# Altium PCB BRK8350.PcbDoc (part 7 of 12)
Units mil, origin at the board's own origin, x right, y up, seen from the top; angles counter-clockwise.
Board outline 9448.82 x 5905.51 mil, 8 copper layers (L1-TOP, L2-GND, L3-SIG, L4-GND, L5-PWR, L6-PWR, L7-GND, L8-BOT), stack 57.69 mil thick; 288 components, 543 nets, 1891 pads, 2032 vias.
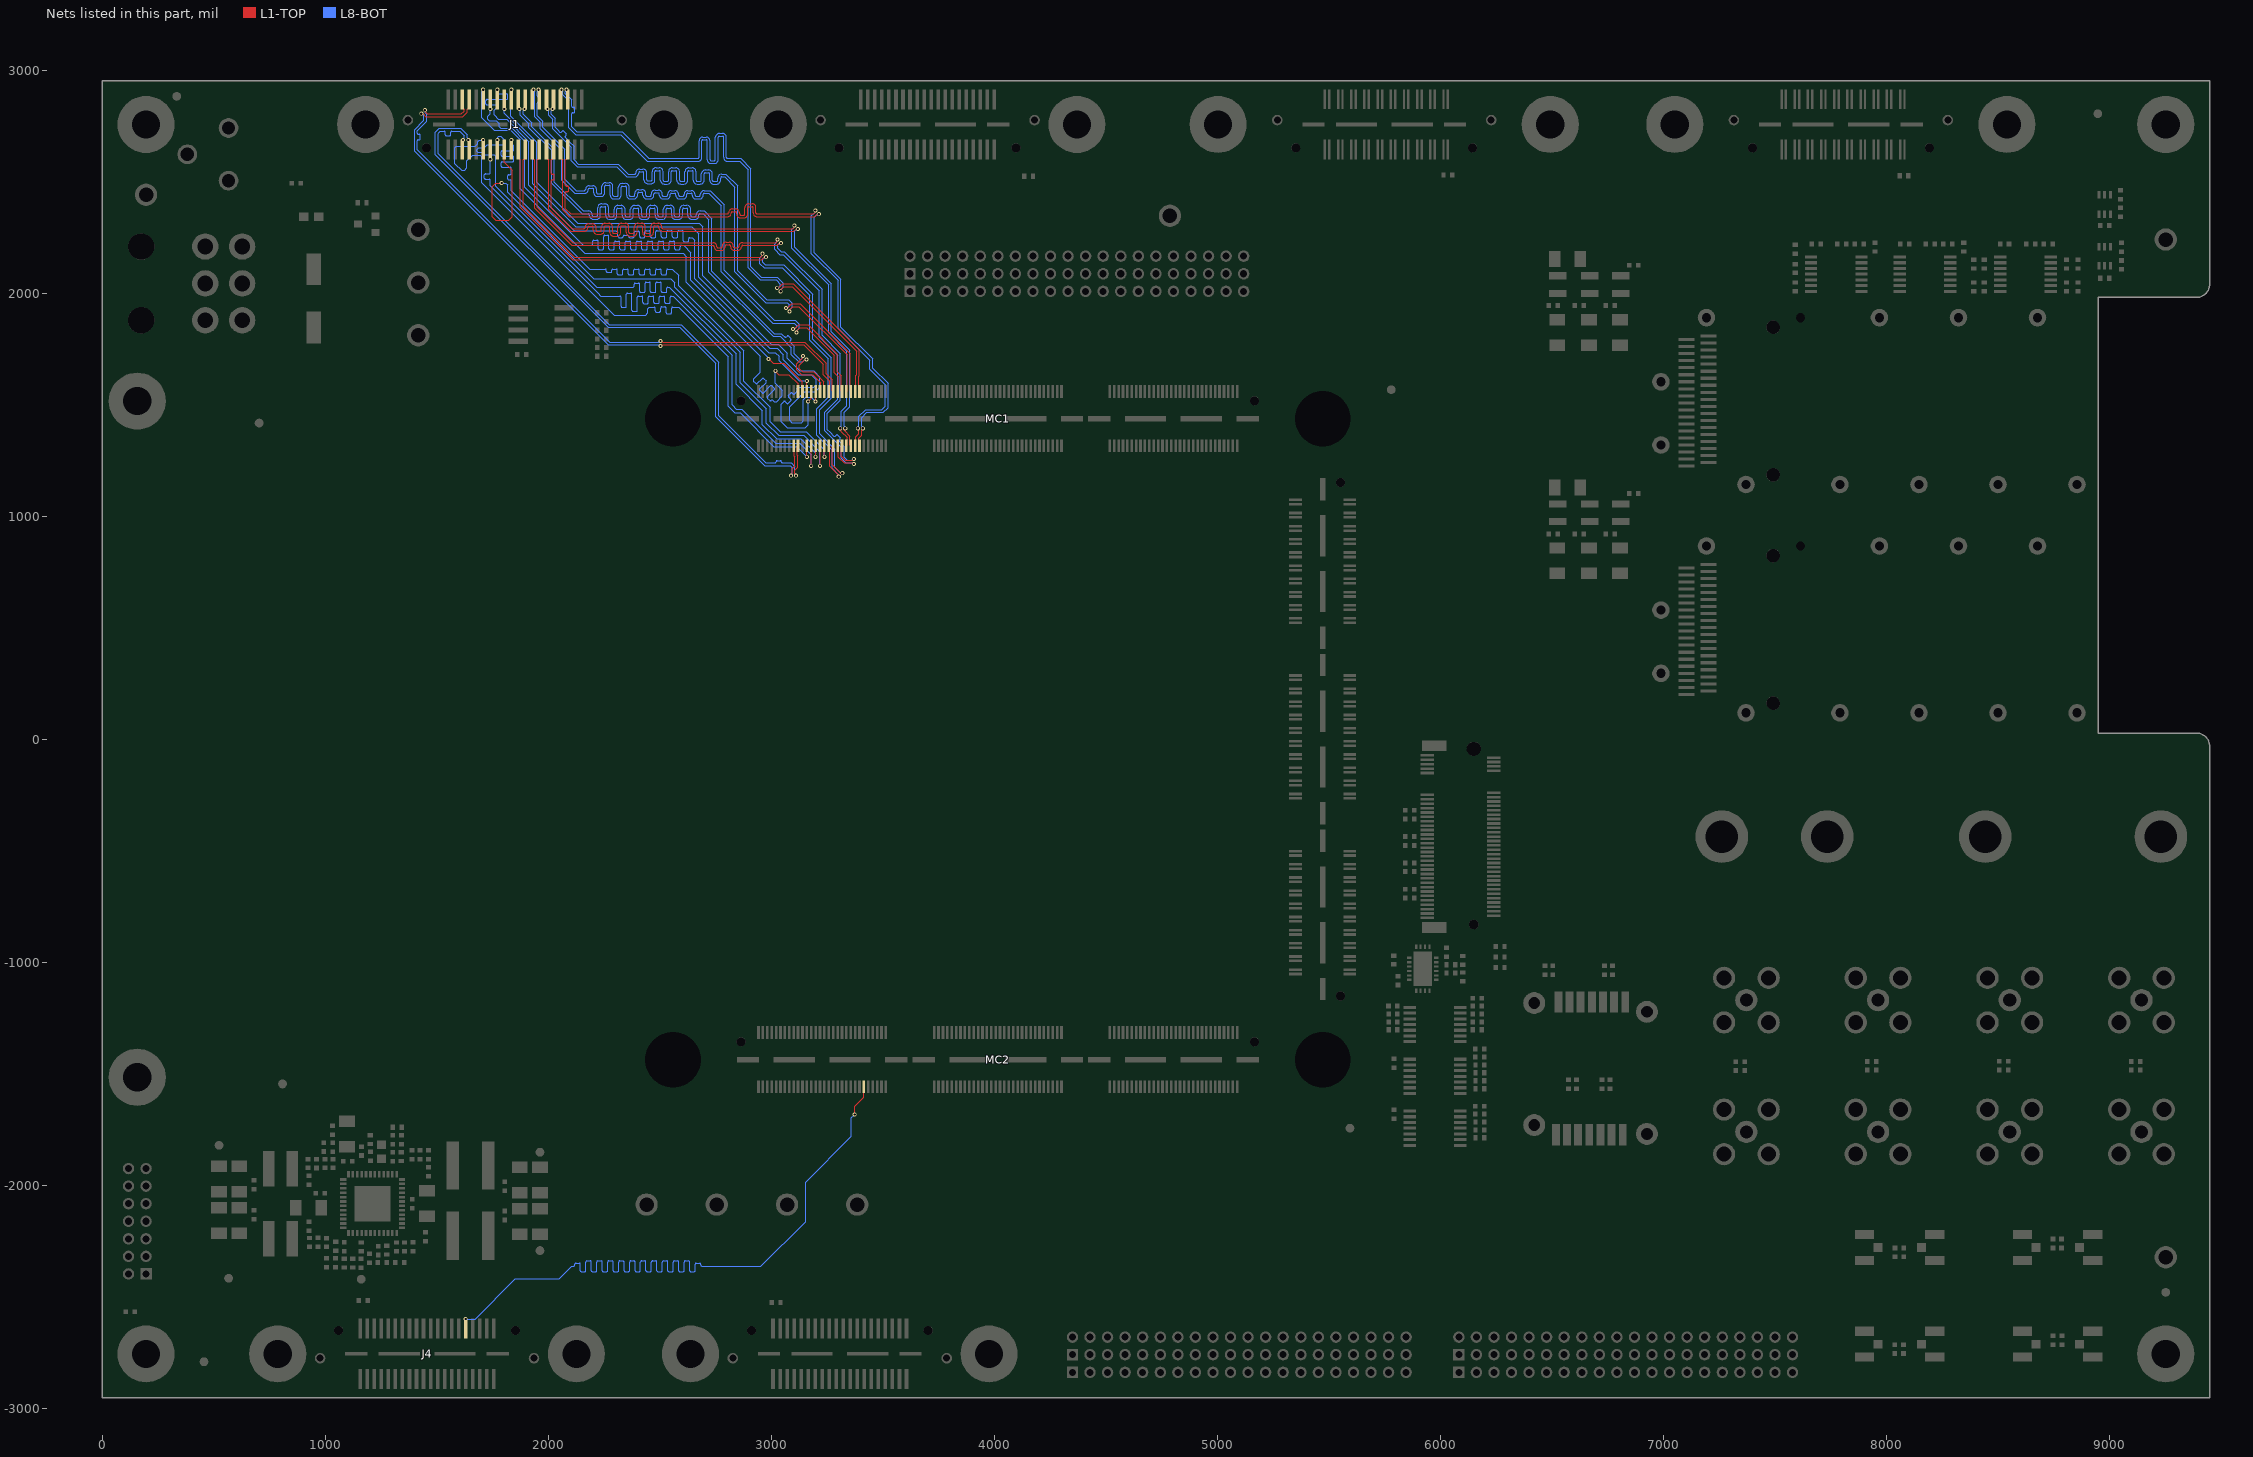
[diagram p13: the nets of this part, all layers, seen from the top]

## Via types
v1: diameter 18, hole 10, L1-TOP to L8-BOT, tented both sides, 2032 vias

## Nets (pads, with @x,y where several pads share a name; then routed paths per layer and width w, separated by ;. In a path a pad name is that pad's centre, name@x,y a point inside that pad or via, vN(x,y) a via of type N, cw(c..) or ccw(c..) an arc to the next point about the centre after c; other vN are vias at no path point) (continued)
PORTB_S27: J4.32 MC2.50 | length 3378.9
  L1-TOP w4.5: v1(3374.02,-1683.29) 3374.02,-1646.26 3415.37,-1604.9 MC2.50@3415.37,-1558.65
  L8-BOT w4.5: v1(1630.04,-2599.76) 1671.9,-2599.76 1852.83,-2418.83 2049.72,-2418.83 2106.34,-2362.2 2112.52,-2362.2 2114.77,-2362.2 ccw(c2114.77,-2357.3) 2119.67,-2357.3 2119.67,-2353.77 cw(c2124.57,-2353.77) 2124.57,-2348.87 2139.27,-2348.87 cw(c2139.27,-2353.77) 2144.17,-2353.77 2144.17,-2382.3 ccw(c2149.07,-2382.3) 2149.07,-2387.2 2163.77,-2387.2 ccw(c2163.77,-2382.3) 2168.67,-2382.3 2168.67,-2344.23 cw(c2173.57,-2344.23) 2173.57,-2339.33 2188.27,-2339.33 cw(c2188.27,-2344.23) 2193.17,-2344.23 2193.17,-2382.3 ccw(c2198.07,-2382.3) 2198.07,-2387.2 2212.77,-2387.2 ccw(c2212.77,-2382.3) 2217.67,-2382.3 2217.67,-2344.23 cw(c2222.57,-2344.23) 2222.57,-2339.33 2237.27,-2339.33 cw(c2237.27,-2344.23) 2242.17,-2344.23 2242.17,-2382.3 ccw(c2247.07,-2382.3) 2247.07,-2387.2 2261.77,-2387.2 ccw(c2261.77,-2382.3) 2266.67,-2382.3 2266.67,-2344.23 cw(c2271.57,-2344.23) 2271.57,-2339.33 2286.27,-2339.33 cw(c2286.27,-2344.23) 2291.17,-2344.23 2291.17,-2382.3 ccw(c2296.07,-2382.3) 2296.07,-2387.2 2310.77,-2387.2 ccw(c2310.77,-2382.3) 2315.67,-2382.3 2315.67,-2344.23 cw(c2320.57,-2344.23) 2320.57,-2339.33 2335.27,-2339.33 cw(c2335.27,-2344.23) 2340.17,-2344.23 2340.17,-2382.3 ccw(c2345.07,-2382.3) 2345.07,-2387.2 2359.77,-2387.2 ccw(c2359.77,-2382.3) 2364.67,-2382.3 2364.67,-2344.23 cw(c2369.57,-2344.23) 2369.57,-2339.33 2384.27,-2339.33 cw(c2384.27,-2344.23) 2389.17,-2344.23 2389.17,-2382.3 ccw(c2394.07,-2382.3) 2394.07,-2387.2 2408.77,-2387.2 ccw(c2408.77,-2382.3) 2413.67,-2382.3 2413.67,-2344.23 cw(c2418.57,-2344.23) 2418.57,-2339.33 2433.27,-2339.33 cw(c2433.27,-2344.23) 2438.17,-2344.23 2438.17,-2382.3 ccw(c2443.07,-2382.3) 2443.07,-2387.2 2457.77,-2387.2 ccw(c2457.77,-2382.3) 2462.67,-2382.3 2462.67,-2344.23 cw(c2467.57,-2344.23) 2467.57,-2339.33 2482.27,-2339.33 cw(c2482.27,-2344.23) 2487.17,-2344.23 2487.17,-2382.3 ccw(c2492.07,-2382.3) 2492.07,-2387.2 2506.77,-2387.2 ccw(c2506.77,-2382.3) 2511.67,-2382.3 2511.67,-2344.23 cw(c2516.57,-2344.23) 2516.57,-2339.33 2531.27,-2339.33 cw(c2531.27,-2344.23) 2536.17,-2344.23 2536.17,-2382.3 ccw(c2541.07,-2382.3) 2541.07,-2387.2 2555.77,-2387.2 ccw(c2555.77,-2382.3) 2560.67,-2382.3 2560.67,-2344.23 cw(c2565.57,-2344.23) 2565.57,-2339.33 2580.27,-2339.33 cw(c2580.27,-2344.23) 2585.17,-2344.23 2585.17,-2382.3 ccw(c2590.07,-2382.3) 2590.07,-2387.2 2604.77,-2387.2 ccw(c2604.77,-2382.3) 2609.67,-2382.3 2609.67,-2344.23 cw(c2614.57,-2344.23) 2614.57,-2339.33 2629.27,-2339.33 cw(c2629.27,-2344.23) 2634.17,-2344.23 2634.17,-2382.3 ccw(c2639.07,-2382.3) 2639.07,-2387.2 2653.77,-2387.2 ccw(c2653.77,-2382.3) 2658.67,-2382.3 2658.67,-2353.66 cw(c2663.57,-2353.66) 2663.57,-2348.76 2678.27,-2348.76 cw(c2678.27,-2353.66) 2683.17,-2353.66 2683.17,-2357.3 ccw(c2688.07,-2357.3) 2688.07,-2362.2 2755.91,-2362.2 2953.94,-2362.2 ; 2955.32,-2360.83 2953.94,-2362.2 ; v1(3374.02,-1683.29) 3359.67,-1697.64 3359.67,-1781.45 3153.54,-1987.58 3153.54,-2162.6 2953.94,-2362.2
PORTC_C2P_CLKN: J1.36 MC1.20 | length 2791.7
  L1-TOP w4.2: v1(3111.25,1181.1) 3111.25,1184.03 3106.3,1188.98 3106.3,1206.59 3118.98,1219.27 3118.98,1271.53 3116.55,1273.96 3116.55,1311.83 MC1.20@3120.09,1315.37
  L8-BOT w4.2: v1(1618.46,2686.46) 1618.46,2690.2 1623.69,2695.43 1623.69,2705.34 1603.62,2725.42 1582.48,2725.42 1567.44,2725.42 ccw(c1567.44,2720.58) 1562.6,2720.58 1562.6,2710.76 cw(c1557.76,2710.76) 1557.76,2705.92 1543.24,2705.92 cw(c1543.24,2710.76) 1538.4,2710.76 1538.4,2720.58 ccw(c1533.56,2720.58) 1533.56,2725.42 1516,2725.42 1509.68,2719.09 1505.88,2715.3 1505.88,2625.74 2273.35,1858.27 2595.94,1858.27 2764.57,1689.64 2764.57,1450.65 2953,1262.21 2976.04,1239.17 2988.19,1239.17 3016.49,1239.17 ccw(c3016.49,1244.01) 3021.33,1244.01 cw(c3026.17,1244.01) 3026.17,1248.85 3040.69,1248.85 cw(c3040.69,1244.01) 3045.53,1244.01 ccw(c3050.37,1244.01) 3050.37,1239.17 3076.67,1239.17 3089.36,1239.17 3106.3,1222.24 3106.3,1189.79 3111.25,1184.84 v1(3111.25,1181.1)
PORTC_C2P_CLKP: J1.34 MC1.18 | length 2791.7
  L1-TOP w4.2: v1(3088.75,1181.1) 3088.75,1184.03 3093.7,1188.98 3093.7,1211.81 3106.38,1224.49 3106.38,1266.31 3103.95,1268.74 3103.95,1311.83 MC1.18@3100.41,1315.37
  L8-BOT w4.2: v1(1641.53,2686.46) 1641.53,2690.2 1636.29,2695.43 1636.29,2710.56 1608.84,2738.02 1510.78,2738.02 1500.77,2728 1493.28,2720.52 1493.28,2704.84 1493.28,2620.52 1561.63,2552.17 2268.13,1845.67 2590.72,1845.67 2751.97,1684.42 2751.97,1445.43 2905.51,1291.88 2935.18,1262.21 2970.82,1226.57 3084.15,1226.57 3093.7,1217.02 3093.7,1189.79 3088.75,1184.84 v1(3088.75,1181.1)
PORTC_P2C_CLKN: J1.35 MC1.35 | length 2839.8
  L1-TOP w4.2: v1(1446.88,2819.96) 1447.83,2819.01 1447.83,2812.01 1456.63,2803.21 1610.55,2803.21 1623.64,2816.31 1623.64,2823.6 1621.18,2826.06 1620.09,2826.06 1614.19,2831.96 J1.35@1614.19,2868.71 ; v1(2503.94,1785.27) 2507.67,1785.27 2512.62,1780.32 3150.65,1780.32 3245.85,1685.11 3245.85,1638.71 3250.71,1633.86 3250.8,1633.86 3274.03,1610.63 3274.03,1562.22 MC1.35@3277.57,1558.68
  L8-BOT w4.2: v1(1446.88,2819.96) 1448.13,2818.71 1448.13,2808.86 1454.72,2802.27 1454.72,2769.38 1413.19,2727.85 1413.19,2723.96 1413.19,2716.64 ccw(c1418.03,2716.64) 1418.03,2711.8 1421.7,2711.8 cw(c1421.7,2706.96) 1426.54,2706.96 1426.53,2692.44 cw(c1421.7,2692.44) 1421.7,2687.6 1418.03,2687.6 ccw(c1418.03,2682.76) 1413.19,2682.76 1413.19,2656.46 1413.19,2641.93 1454.72,2600.39 1502.95,2552.17 2274.8,1780.32 2495.25,1780.32 2500.2,1785.27 v1(2503.94,1785.27)
PORTC_P2C_CLKP: J1.33 MC1.33 | length 2840.6
  L1-TOP w4.2: v1(1430.97,2804.05) 1431.92,2803.1 1438.93,2803.1 1451.41,2790.61 1615.77,2790.61 1636.24,2811.09 1636.24,2823.6 1638.7,2826.06 1639.79,2826.06 1645.69,2831.96 J1.33@1645.69,2868.71 ; v1(2503.94,1762.77) 2507.67,1762.77 2512.62,1767.72 3145.43,1767.72 3233.25,1679.9 3233.25,1633.86 3233.25,1633.5 3245.49,1621.26 3245.58,1621.26 3261.43,1605.41 3261.43,1562.22 MC1.33@3257.89,1558.68
  L8-BOT w4.2: v1(1430.97,2804.05) 1434.7,2804.05 1439.25,2799.51 1439.66,2799.51 1442.12,2797.05 1442.12,2774.6 1400.59,2733.07 1400.59,2636.71 1454.72,2582.57 1485.13,2552.17 2269.58,1767.72 2495.25,1767.72 2500.2,1762.77 v1(2503.94,1762.77)
PORTC_S0_D0P: J1.5 MC1.45 | length 2793.1
  L1-TOP w4.2: v1(3042.35,2007.79) 3043.31,2008.75 3043.31,2015.75 3056.72,2029.16 3093.06,2029.16 3382.24,1739.99 3382.24,1633.86 3379.81,1631.43 3379.81,1562.48 MC1.45@3376,1558.68
  L8-BOT w4.2: v1(2082.53,2912.06) 2082.53,2908.33 2077.29,2903.09 2077.29,2894.33 2105.14,2866.48 2105.14,2856.88 2105.14,2837.74 ccw(c2109.98,2837.74) 2109.98,2832.9 2114.87,2832.9 cw(c2114.87,2828.06) 2119.71,2828.06 2119.71,2813.54 cw(c2114.87,2813.54) 2114.87,2808.7 2109.98,2808.7 ccw(c2109.98,2803.86) 2105.14,2803.86 2105.14,2777.56 2105.14,2745.34 2128.21,2722.27 2330.98,2722.27 2449.63,2603.62 2579.72,2603.62 2671.21,2603.62 ccw(c2671.21,2608.46) 2676.05,2608.46 2676.05,2682.04 cw(c2693.49,2682.04) 2693.49,2699.48 2708.01,2699.48 cw(c2708.01,2682.04) 2725.45,2682.04 2725.45,2598.64 ccw(c2730.29,2598.64) 2730.29,2593.8 2744.81,2593.8 ccw(c2744.81,2598.64) 2749.65,2598.64 2749.65,2698.32 cw(c2767.09,2698.32) 2767.09,2715.76 2781.61,2715.76 cw(c2781.61,2698.32) 2799.05,2698.32 2799.05,2608.46 ccw(c2803.89,2608.46) 2803.89,2603.62 2849.1,2603.62 2862.91,2603.62 2908.7,2557.84 2908.7,2117.7 2954.75,2071.66 3026.77,2071.66 3053.36,2045.06 3053.36,2025.8 3044.99,2017.43 3044.99,2010.43 v1(3042.35,2007.79)
PORTC_S1_D1P: J1.6 MC1.46 | length 2840.6
  L1-TOP w4.2: J1.6@2086.69,2643.11 2086.69,2606.36 2080.79,2600.46 2079.7,2600.46 2077.24,2598 2077.24,2509.43 2077.24,2484.39 ccw(c2082.08,2484.39) 2082.08,2479.55 2087,2479.55 cw(c2087,2474.71) 2091.84,2474.71 2091.84,2460.19 cw(c2087,2460.19) 2087,2455.35 2082.08,2455.35 ccw(c2082.08,2450.51) 2077.24,2450.51 2077.24,2424.21 2077.24,2377.76 2099.88,2355.12 2750,2355.12 2803.42,2355.12 ccw(c2803.42,2359.96) 2808.26,2359.96 cw(c2825.7,2359.96) 2825.7,2377.4 2840.22,2377.4 cw(c2840.22,2359.96) 2857.66,2359.96 2857.66,2354.72 ccw(c2862.5,2354.72) 2862.5,2349.88 2877.02,2349.88 ccw(c2877.02,2354.72) 2881.86,2354.72 2881.86,2383.26 cw(c2899.3,2383.26) 2899.3,2400.7 2913.82,2400.7 cw(c2913.82,2383.26) 2931.26,2383.26 2931.26,2359.96 ccw(c2936.1,2359.96) 2936.1,2355.12 2981.3,2355.12 3189.77,2355.12 3199.05,2364.4 3197.29,2366.16 v1(3197.29,2369.64) ; MC1.46@3376,1315.37 3379.54,1318.91 3379.54,1355.43 3392.91,1368.8 3392.91,1385.02 3387.96,1389.97 v1(3387.96,1393.7)
  L8-BOT w4.2: v1(3197.29,2369.64) 3194.65,2367 3194.65,2360 3180.31,2345.67 3180.31,2175.88 3299.38,2056.81 3299.38,2027.84 3299.38,1842.07 3397.73,1743.72 3442.12,1699.33 3442.12,1658.27 3510.83,1589.57 3510.83,1492.13 3495.92,1477.22 3422.98,1477.22 3392.91,1447.15 3392.91,1402.39 3387.96,1397.44 v1(3387.96,1393.7)
PORTC_S2_D0N: J1.7 MC1.47 | length 2792.9
  L1-TOP w4.2: v1(3026.44,2023.7) 3027.4,2024.66 3034.4,2024.66 3051.5,2041.76 3098.28,2041.76 3394.84,1745.21 3394.84,1628.64 3392.41,1626.21 3392.41,1561.96 MC1.47@3395.69,1558.68
  L8-BOT w4.2: v1(2059.46,2912.06) 2059.46,2908.33 2064.69,2903.09 2064.69,2889.11 2092.54,2861.26 2092.54,2740.12 2123,2709.67 2325.76,2709.67 2444.41,2591.02 2579.72,2591.02 2671.21,2591.02 ccw(c2671.21,2608.46) 2688.65,2608.46 2688.65,2682.04 cw(c2693.49,2682.04) 2693.49,2686.88 2708.01,2686.88 cw(c2708.01,2682.04) 2712.85,2682.04 2712.85,2598.64 ccw(c2730.29,2598.64) 2730.29,2581.2 2744.81,2581.2 ccw(c2744.81,2598.64) 2762.25,2598.64 2762.25,2698.32 cw(c2767.09,2698.32) 2767.09,2703.16 2781.61,2703.15 cw(c2781.61,2698.32) 2786.45,2698.32 2786.45,2608.46 ccw(c2803.89,2608.46) 2803.89,2591.02 2849.1,2591.02 2857.7,2591.02 2896.1,2552.62 2896.1,2112.48 2949.53,2059.06 3021.55,2059.06 3040.76,2039.84 3040.76,2031.02 3036.08,2026.34 3029.08,2026.34 v1(3026.44,2023.7)
PORTC_S3_D1N: J1.8 MC1.48 | length 2840.6
  L1-TOP w4.2: J1.8@2055.19,2643.11 2055.19,2606.36 2061.09,2600.46 2062.18,2600.46 2064.64,2598 2064.64,2372.54 2094.66,2342.52 2750,2342.52 2803.42,2342.52 ccw(c2803.42,2359.96) 2820.86,2359.96 cw(c2825.7,2359.96) 2825.7,2364.8 2840.22,2364.8 cw(c2840.22,2359.96) 2845.06,2359.96 2845.06,2354.72 ccw(c2862.5,2354.72) 2862.5,2337.28 2877.02,2337.28 ccw(c2877.02,2354.72) 2894.46,2354.72 2894.46,2383.26 cw(c2899.3,2383.26) 2899.3,2388.1 2913.82,2388.1 cw(c2913.82,2383.26) 2918.66,2383.26 2918.66,2359.96 ccw(c2936.1,2359.96) 2936.1,2342.52 2981.3,2342.52 3194.98,2342.52 3207.96,2355.49 3211.44,2355.49 v1(3213.2,2353.73) ; MC1.48@3395.69,1315.37 3392.14,1318.91 3392.14,1350.21 3405.51,1363.58 3405.51,1385.02 3410.46,1389.97 v1(3410.46,1393.7)
  L8-BOT w4.2: v1(3213.2,2353.73) 3210.56,2351.09 3203.56,2351.09 3192.91,2340.45 3192.91,2181.1 3311.98,2062.03 3311.98,1847.29 3454.72,1704.55 3454.72,1663.49 3523.43,1594.79 3523.43,1486.91 3501.14,1464.62 3428.2,1464.62 3405.51,1441.93 3405.51,1402.39 3410.46,1397.44 v1(3410.46,1393.7)
PORTC_S4_D2P: J1.9 MC1.41 | length 2793.1
  L1-TOP w4.2: v1(3081.72,1917.24) 3082.68,1918.2 3082.68,1925.2 3096.81,1939.33 3123.78,1939.33 3340.44,1722.67 3340.44,1562.48 MC1.41@3336.63,1558.68
  L8-BOT w4.2: v1(2019.43,2825.35) 2019.43,2821.61 2014.19,2816.38 2014.19,2801.72 2032.22,2783.69 2032.22,2742.52 2043.51,2731.23 2052.66,2722.09 ccw(c2056.08,2725.51) 2059.5,2722.09 2062.95,2725.53 cw(c2066.37,2722.11) 2069.8,2725.53 2080.06,2715.27 cw(c2076.64,2711.84) 2080.06,2708.42 2076.62,2704.97 ccw(c2080.04,2701.55) 2076.62,2698.13 2095.21,2679.53 2115.7,2659.04 2115.7,2597.88 2135.04,2578.54 2247.05,2578.54 2312.99,2578.54 2358.27,2533.27 2387.55,2533.27 ccw(c2387.55,2538.11) 2392.39,2538.11 cw(c2409.83,2538.11) 2409.83,2555.55 2424.35,2555.55 cw(c2424.35,2538.11) 2441.79,2538.11 2441.79,2507.94 ccw(c2446.63,2507.94) 2446.63,2503.1 2461.15,2503.1 ccw(c2461.15,2507.94) 2465.99,2507.94 2465.99,2544.38 cw(c2483.43,2544.38) 2483.43,2561.82 2497.95,2561.82 cw(c2497.95,2544.38) 2515.39,2544.38 2515.39,2506.29 ccw(c2520.23,2506.29) 2520.23,2501.45 2534.75,2501.45 ccw(c2534.75,2506.29) 2539.59,2506.29 2539.59,2544.38 cw(c2557.03,2544.38) 2557.03,2561.82 2571.55,2561.82 cw(c2571.55,2544.38) 2588.99,2544.38 2588.99,2506.29 ccw(c2593.83,2506.29) 2593.83,2501.45 2608.35,2501.45 ccw(c2608.35,2506.29) 2613.19,2506.29 2613.19,2544.38 cw(c2630.63,2544.38) 2630.63,2561.82 2645.15,2561.82 cw(c2645.15,2544.38) 2662.59,2544.38 2662.59,2506.29 ccw(c2667.43,2506.29) 2667.43,2501.45 2681.95,2501.45 ccw(c2681.95,2506.29) 2686.79,2506.29 2686.79,2534.56 cw(c2704.23,2534.56) 2704.23,2552 2718.75,2552 cw(c2718.75,2534.56) 2736.19,2534.56 2736.19,2506.03 ccw(c2741.03,2506.03) 2741.03,2501.19 2755.55,2501.19 ccw(c2755.55,2506.03) 2760.39,2506.03 2760.39,2515.83 cw(c2777.83,2515.83) 2777.83,2533.27 2786.23,2533.27 2796.56,2533.27 2849.41,2480.42 2849.41,2100.48 2979.65,1970.23 3077.85,1970.23 3094.32,1953.76 3094.32,1936.84 3084.36,1926.88 3084.36,1919.88 v1(3081.72,1917.24)
PORTC_S5_D3P: J1.10 MC1.42 | length 2840.2
  L1-TOP w4.2: J1.10@2023.69,2643.11 2023.69,2606.36 2017.79,2600.46 2016.7,2600.46 2014.24,2598 2014.24,2544.29 2014.24,2536.91 ccw(c2019.08,2536.91) 2019.08,2532.07 2023.06,2532.07 cw(c2023.06,2527.23) 2027.9,2527.23 2027.9,2512.71 cw(c2023.06,2512.71) 2023.06,2507.87 2019.08,2507.87 ccw(c2019.08,2503.03) 2014.24,2503.03 2014.24,2476.73 2014.24,2381.64 2106.77,2289.11 2122.67,2289.11 2160.37,2289.11 ccw(c2160.37,2293.95) 2165.21,2293.95 cw(c2182.65,2293.95) 2182.65,2311.39 2197.17,2311.39 cw(c2197.17,2293.95) 2214.61,2293.95 2214.61,2281.54 ccw(c2219.45,2281.54) 2219.45,2276.7 2233.97,2276.7 ccw(c2233.97,2281.54) 2238.81,2281.54 2238.81,2295.88 cw(c2256.25,2295.88) 2256.25,2313.32 2270.77,2313.32 cw(c2270.77,2295.88) 2288.21,2295.88 2288.21,2272.73 ccw(c2293.05,2272.73) 2293.05,2267.89 2307.57,2267.89 ccw(c2307.57,2272.73) 2312.41,2272.73 2312.41,2295.88 cw(c2329.85,2295.88) 2329.85,2313.32 2344.37,2313.32 cw(c2344.37,2295.88) 2361.81,2295.88 2361.81,2272.73 ccw(c2366.65,2272.73) 2366.65,2267.89 2381.17,2267.89 ccw(c2381.17,2272.73) 2386.01,2272.73 2386.01,2295.88 cw(c2403.45,2295.88) 2403.45,2313.32 2417.97,2313.32 cw(c2417.97,2295.88) 2435.41,2295.88 2435.41,2272.73 ccw(c2440.25,2272.73) 2440.25,2267.89 2454.77,2267.89 ccw(c2454.77,2272.73) 2459.61,2272.73 2459.61,2295.88 cw(c2477.05,2295.88) 2477.05,2313.32 2491.57,2313.32 cw(c2491.57,2295.88) 2509.01,2295.88 2509.01,2293.95 ccw(c2513.85,2293.95) 2513.85,2289.11 2559.06,2289.11 3096.2,2289.11 3102.36,2295.28 3102.36,2302.28 v1(3103.32,2303.23) ; v1(3309.22,1393.7) 3311.68,1391.24 3314.17,1391.24 3314.17,1378.74 3340.17,1352.74 3340.17,1318.91 MC1.42@3336.63,1315.37
  L8-BOT w4.2: v1(3103.32,2303.23) 3100.68,2300.59 3100.68,2293.59 3092.31,2285.22 3092.31,2200.9 3256.83,2036.38 3256.83,1822.03 3339.51,1739.35 3339.51,1495.12 3314.17,1469.79 3314.17,1402.39 3309.22,1397.44 v1(3309.22,1393.7)
PORTC_S6_D2N: J1.11 MC1.43 | length 2792.9
  L1-TOP w4.2: v1(3065.81,1933.15) 3066.77,1934.11 3073.77,1934.11 3091.59,1951.93 3129,1951.93 3353.04,1727.89 3353.04,1561.96 MC1.43@3356.31,1558.68
  L8-BOT w4.2: v1(1996.36,2825.35) 1996.36,2821.61 2001.59,2816.38 2001.59,2796.5 2019.62,2778.47 2019.62,2737.3 2086.3,2670.62 2103.1,2653.82 2103.1,2592.66 2129.82,2565.94 2247.05,2565.94 2307.77,2565.94 2353.05,2520.67 2358.27,2520.67 2387.55,2520.67 ccw(c2387.55,2538.11) 2404.99,2538.11 cw(c2409.83,2538.11) 2409.83,2542.95 2424.35,2542.95 cw(c2424.35,2538.11) 2429.19,2538.11 2429.19,2507.94 ccw(c2446.63,2507.94) 2446.63,2490.5 2461.15,2490.5 ccw(c2461.15,2507.94) 2478.59,2507.94 2478.59,2544.38 cw(c2483.43,2544.38) 2483.43,2549.22 2497.95,2549.22 cw(c2497.95,2544.38) 2502.79,2544.38 2502.79,2506.29 ccw(c2520.23,2506.29) 2520.23,2488.85 2534.75,2488.85 ccw(c2534.75,2506.29) 2552.19,2506.29 2552.19,2544.38 cw(c2557.03,2544.38) 2557.03,2549.22 2571.55,2549.22 cw(c2571.55,2544.38) 2576.39,2544.38 2576.39,2506.29 ccw(c2593.83,2506.29) 2593.83,2488.85 2608.35,2488.85 ccw(c2608.35,2506.29) 2625.79,2506.29 2625.79,2544.38 cw(c2630.63,2544.38) 2630.63,2549.22 2645.15,2549.22 cw(c2645.15,2544.38) 2649.99,2544.38 2649.99,2506.29 ccw(c2667.43,2506.29) 2667.43,2488.85 2681.95,2488.85 ccw(c2681.95,2506.29) 2699.39,2506.29 2699.39,2534.56 cw(c2704.23,2534.56) 2704.23,2539.4 2718.75,2539.4 cw(c2718.75,2534.56) 2723.59,2534.56 2723.59,2506.03 ccw(c2741.03,2506.03) 2741.03,2488.59 2755.55,2488.59 ccw(c2755.55,2506.03) 2772.99,2506.03 2772.99,2515.83 cw(c2777.83,2515.83) 2777.83,2520.67 2786.23,2520.67 2791.34,2520.67 2836.81,2475.2 2836.81,2095.26 2974.43,1957.63 3072.63,1957.63 3081.72,1948.54 3081.72,1942.06 3075.45,1935.79 3068.45,1935.79 v1(3065.81,1933.15)
PORTC_S7_D3N: J1.12 MC1.44 | length 2842.1
  L1-TOP w4.2: J1.12@1992.19,2643.11 1992.19,2606.36 1998.09,2600.46 1999.18,2600.46 2001.64,2598 2001.64,2376.42 2101.55,2276.51 2122.67,2276.51 2160.37,2276.51 ccw(c2160.37,2293.95) 2177.81,2293.95 cw(c2182.65,2293.95) 2182.65,2298.79 2197.17,2298.79 cw(c2197.17,2293.95) 2202.01,2293.95 2202.01,2281.54 ccw(c2219.45,2281.54) 2219.45,2264.1 2233.97,2264.1 ccw(c2233.97,2281.54) 2251.41,2281.54 2251.41,2295.88 cw(c2256.25,2295.88) 2256.25,2300.72 2270.77,2300.72 cw(c2270.77,2295.88) 2275.61,2295.88 2275.61,2272.73 ccw(c2293.05,2272.73) 2293.05,2255.29 2307.57,2255.29 ccw(c2307.57,2272.73) 2325.01,2272.73 2325.01,2295.88 cw(c2329.85,2295.88) 2329.85,2300.72 2344.37,2300.72 cw(c2344.37,2295.88) 2349.21,2295.88 2349.21,2272.73 ccw(c2366.65,2272.73) 2366.65,2255.29 2381.17,2255.29 ccw(c2381.17,2272.73) 2398.61,2272.73 2398.61,2295.88 cw(c2403.45,2295.88) 2403.45,2300.72 2417.97,2300.72 cw(c2417.97,2295.88) 2422.81,2295.88 2422.81,2272.73 ccw(c2440.25,2272.73) 2440.25,2255.29 2454.77,2255.29 ccw(c2454.77,2272.73) 2472.21,2272.73 2472.21,2295.88 cw(c2477.05,2295.88) 2477.05,2300.72 2491.57,2300.72 cw(c2491.57,2295.88) 2496.41,2295.88 2496.41,2293.95 ccw(c2513.85,2293.95) 2513.85,2276.51 2559.06,2276.51 3101.42,2276.51 3111.27,2286.37 3118.27,2286.37 v1(3119.23,2287.32) ; v1(3331.72,1393.7) 3329.23,1393.7 3326.77,1391.24 3326.77,1383.96 3352.77,1357.96 3352.77,1318.91 MC1.44@3356.31,1315.37
  L8-BOT w4.2: v1(3119.23,2287.32) 3116.59,2284.68 3109.59,2284.68 3104.91,2280 3104.91,2206.12 3269.43,2041.6 3269.43,1827.25 3352.11,1744.57 3352.11,1489.9 3326.77,1464.57 3326.77,1402.39 3331.72,1397.44 v1(3331.72,1393.7)
PORTC_S8_D4P: J1.13 MC1.37 | length 2793
  L1-TOP w4.2: v1(3113.22,1822.75) 3114.17,1823.71 3114.17,1830.71 3127.87,1844.41 3159.59,1844.41 3283.46,1720.53 3283.46,1642.4 3300.8,1625.06 3300.8,1562.22 MC1.37@3297.26,1558.68
  L8-BOT w4.2: v1(1956.53,2912.06) 1956.53,2908.33 1951.29,2903.09 1951.29,2894.69 1951.29,2885.53 ccw(c1956.13,2885.53) 1956.13,2880.69 1961.05,2880.69 cw(c1961.05,2875.85) 1965.89,2875.85 1965.89,2861.33 cw(c1961.05,2861.33) 1961.05,2856.49 1956.13,2856.49 ccw(c1956.13,2851.65) 1951.29,2851.65 1951.29,2825.35 1951.29,2795.72 1976.12,2770.89 1976.12,2742.52 2073.8,2644.84 2073.8,2510.47 2124.63,2459.65 2162.34,2459.65 ccw(c2162.34,2464.49) 2167.18,2464.49 cw(c2184.62,2464.49) 2184.62,2481.93 2199.14,2481.93 cw(c2199.14,2464.49) 2216.58,2464.49 2216.58,2450.65 ccw(c2221.42,2450.65) 2221.42,2445.81 2235.94,2445.81 ccw(c2235.94,2450.65) 2240.78,2450.65 2240.78,2478.24 cw(c2258.22,2478.24) 2258.22,2495.68 2272.74,2495.68 cw(c2272.74,2478.24) 2290.18,2478.24 2290.18,2439.49 ccw(c2295.02,2439.49) 2295.02,2434.65 2309.54,2434.65 ccw(c2309.54,2439.49) 2314.38,2439.49 2314.38,2474.03 cw(c2331.82,2474.03) 2331.82,2491.47 2346.34,2491.47 cw(c2346.34,2474.03) 2363.78,2474.03 2363.78,2439.49 ccw(c2368.62,2439.49) 2368.62,2434.65 2383.14,2434.65 ccw(c2383.14,2439.49) 2387.98,2439.49 2387.98,2446.19 cw(c2405.42,2446.19) 2405.42,2463.63 2419.94,2463.63 cw(c2419.94,2446.19) 2437.38,2446.19 2437.38,2439.49 ccw(c2442.22,2439.49) 2442.22,2434.65 2456.74,2434.65 ccw(c2456.74,2439.49) 2461.58,2439.49 2461.58,2443.86 cw(c2479.02,2443.86) 2479.02,2461.3 2493.54,2461.3 cw(c2493.54,2443.86) 2510.98,2443.86 2510.98,2439.49 ccw(c2515.82,2439.49) 2515.82,2434.65 2530.34,2434.65 ccw(c2530.34,2439.49) 2535.18,2439.49 2535.18,2442.21 cw(c2552.62,2442.21) 2552.62,2459.65 2567.14,2459.65 cw(c2567.14,2442.21) 2584.58,2442.21 2584.58,2439.49 ccw(c2589.42,2439.49) 2589.42,2434.65 2603.94,2434.65 ccw(c2603.94,2439.49) 2608.78,2439.49 2608.78,2442.21 cw(c2626.22,2442.21) 2626.22,2459.65 2640.74,2459.65 cw(c2640.74,2442.21) 2658.18,2442.21 2658.18,2439.49 ccw(c2663.02,2439.49) 2663.02,2434.65 2677.54,2434.65 ccw(c2677.54,2439.49) 2682.38,2439.49 2682.38,2442.21 cw(c2699.82,2442.21) 2699.82,2459.65 2708.22,2459.65 2725.64,2459.65 2789.37,2395.91 2789.37,2101.26 3012.68,1877.95 3107.6,1877.95 3126.24,1859.32 3126.24,1842.77 3118.8,1835.33 3115.86,1832.39 3115.86,1825.39 v1(3113.22,1822.75)
PORTC_S9_D5P: J1.14 MC1.38 | length 2840.5
  L1-TOP w4.2: J1.14@1960.69,2643.11 1960.69,2606.36 1954.79,2600.46 1953.7,2600.46 1951.24,2598 1951.24,2385.53 2110.68,2226.09 2693.65,2226.09 2738.85,2226.09 cw(c2738.85,2208.65) 2756.29,2208.65 2756.29,2208.53 ccw(c2761.13,2208.53) 2761.13,2203.69 2775.65,2203.69 ccw(c2775.65,2208.53) 2780.49,2208.53 2780.49,2210.92 cw(c2797.93,2210.92) 2797.93,2228.36 2812.45,2228.36 cw(c2812.45,2210.92) 2829.89,2210.92 2829.89,2208.65 ccw(c2834.73,2208.65) 2834.73,2203.81 2849.25,2203.81 ccw(c2849.25,2208.65) 2854.09,2208.65 cw(c2871.53,2208.65) 2871.53,2226.09 2908.57,2226.09 3021.37,2226.09 3029.76,2234.48 3028,2236.24 v1(3028,2239.72) ; MC1.38@3297.26,1315.37 3300.8,1311.83 3300.8,1264.07 3326.54,1238.33 3362.22,1238.33 3367.17,1233.38 v1(3370.09,1233.38)
  L8-BOT w4.2: v1(3028,2239.72) 3025.36,2237.08 3025.36,2230.08 3015.21,2219.93 3015.21,2206.01 3015.4,2205.82 3015.4,2195.57 3038.53,2172.44 3053.84,2172.44 3215.03,2011.25 3215.03,1804.72 3297.71,1722.04 3297.71,1524.19 3239.37,1465.85 3239.37,1382.68 3314.17,1307.88 3314.17,1258.56 3334.4,1238.33 3361.41,1238.33 3366.36,1233.38 v1(3370.09,1233.38)
PORTC_S10_D4N: J1.15 MC1.39 | length 2793
  L1-TOP w4.2: v1(3097.31,1838.66) 3098.26,1839.62 3105.26,1839.62 3122.65,1857.01 3164.81,1857.01 3296.06,1725.75 3296.06,1647.62 3313.4,1630.28 3313.4,1562.22 MC1.39@3316.94,1558.68
  L8-BOT w4.2: v1(1933.46,2912.06) 1933.46,2908.33 1938.69,2903.09 1938.69,2790.5 1963.52,2765.67 1963.52,2737.3 2061.2,2639.62 2061.2,2505.25 2119.41,2447.05 2124.63,2447.05 2162.34,2447.05 ccw(c2162.34,2464.49) 2179.78,2464.49 cw(c2184.62,2464.49) 2184.62,2469.33 2199.14,2469.33 cw(c2199.14,2464.49) 2203.98,2464.49 2203.98,2450.65 ccw(c2221.42,2450.65) 2221.42,2433.21 2235.94,2433.21 ccw(c2235.94,2450.65) 2253.38,2450.65 2253.38,2478.24 cw(c2258.22,2478.24) 2258.22,2483.08 2272.74,2483.08 cw(c2272.74,2478.24) 2277.58,2478.24 2277.58,2439.49 ccw(c2295.02,2439.49) 2295.02,2422.05 2309.54,2422.05 ccw(c2309.54,2439.49) 2326.98,2439.49 2326.98,2474.03 cw(c2331.82,2474.03) 2331.82,2478.87 2346.34,2478.87 cw(c2346.34,2474.03) 2351.18,2474.03 2351.18,2439.49 ccw(c2368.62,2439.49) 2368.62,2422.05 2383.14,2422.05 ccw(c2383.14,2439.49) 2400.58,2439.49 2400.58,2446.19 cw(c2405.42,2446.19) 2405.42,2451.03 2419.94,2451.03 cw(c2419.94,2446.19) 2424.78,2446.19 2424.78,2439.49 ccw(c2442.22,2439.49) 2442.22,2422.05 2456.74,2422.05 ccw(c2456.74,2439.49) 2474.18,2439.49 2474.18,2443.86 cw(c2479.02,2443.86) 2479.02,2448.7 2493.54,2448.7 cw(c2493.54,2443.86) 2498.38,2443.86 2498.38,2439.49 ccw(c2515.82,2439.49) 2515.82,2422.05 2530.34,2422.05 ccw(c2530.34,2439.49) 2547.78,2439.49 2547.78,2442.21 cw(c2552.62,2442.21) 2552.62,2447.05 2567.14,2447.05 cw(c2567.14,2442.21) 2571.98,2442.21 2571.98,2439.49 ccw(c2589.42,2439.49) 2589.42,2422.05 2603.94,2422.05 ccw(c2603.94,2439.49) 2621.38,2439.49 2621.38,2442.21 cw(c2626.22,2442.21) 2626.22,2447.05 2640.74,2447.05 cw(c2640.74,2442.21) 2645.58,2442.21 2645.58,2439.49 ccw(c2663.02,2439.49) 2663.02,2422.05 2677.54,2422.05 ccw(c2677.54,2439.49) 2694.98,2439.49 2694.98,2442.21 cw(c2699.82,2442.21) 2699.82,2447.05 2708.22,2447.05 2720.42,2447.05 2776.77,2390.69 2776.77,2096.04 3007.46,1865.35 3102.38,1865.35 3113.64,1854.1 3113.64,1847.99 3106.95,1841.3 3099.95,1841.3 v1(3097.31,1838.66)
PORTC_S11_D5N: J1.16 MC1.40 | length 2840.6
  L1-TOP w4.2: J1.16@1929.19,2643.11 1929.19,2606.36 1935.09,2600.46 1936.18,2600.46 1938.64,2598 1938.64,2380.31 2105.46,2213.49 2693.65,2213.49 2738.85,2213.49 cw(c2738.85,2208.65) 2743.69,2208.65 2743.69,2208.53 ccw(c2761.13,2208.53) 2761.13,2191.09 2775.65,2191.09 ccw(c2775.65,2208.53) 2793.09,2208.53 2793.09,2210.92 cw(c2797.93,2210.92) 2797.93,2215.76 2812.45,2215.76 cw(c2812.45,2210.92) 2817.29,2210.92 2817.29,2208.65 ccw(c2834.73,2208.65) 2834.73,2191.21 2849.25,2191.21 ccw(c2849.25,2208.65) 2866.69,2208.65 cw(c2871.53,2208.65) 2871.53,2213.49 2908.57,2213.49 3026.59,2213.49 3038.67,2225.57 3042.15,2225.57 v1(3043.91,2223.81) ; MC1.40@3316.94,1315.37 3313.4,1311.83 3313.4,1269.29 3331.76,1250.93 3362.22,1250.93 3367.17,1255.88 v1(3370.09,1255.88)
  L8-BOT w4.2: v1(3043.91,2223.81) 3041.27,2221.17 3034.27,2221.17 3027.81,2214.71 3027.81,2211.23 3028,2211.04 3028,2200.79 3043.74,2185.04 3059.06,2185.04 3227.63,2016.47 3227.63,1809.93 3310.31,1727.26 3310.31,1518.97 3251.97,1460.63 3251.97,1387.9 3261.81,1378.06 3280.73,1359.14 ccw(c3284.15,1362.56) 3287.57,1359.14 3291.07,1362.64 cw(c3294.5,1359.22) 3297.92,1362.64 3308.18,1352.37 cw(c3304.76,1348.95) 3308.18,1345.53 3304.69,1342.03 ccw(c3308.11,1338.6) 3304.69,1335.18 3323.28,1316.58 3326.77,1313.09 3326.77,1263.78 3339.62,1250.93 3361.41,1250.93 3366.36,1255.88 v1(3370.09,1255.88)
PORTC_S12_D6P: J1.17 MC1.29 | length 2793
  L1-TOP w4.2: v1(3142.17,1718.17) 3141.21,1717.22 3141.21,1710.21 3113.38,1682.38 3113.38,1656.2 3135.72,1633.86 3186.23,1633.86 3222.06,1598.03 3222.06,1562.22 MC1.29@3218.52,1558.68
  L8-BOT w4.2: v1(1893.43,2825.35) 1893.43,2821.61 1888.19,2816.38 1888.19,2801.73 1925.74,2764.18 1925.74,2746.64 2027.4,2644.98 2027.4,2497.62 2154.3,2370.72 2156.91,2368.11 2179.96,2368.11 cw(c2179.96,2350.67) 2197.4,2350.67 2197.4,2348.55 ccw(c2202.24,2348.55) 2202.24,2343.71 2216.76,2343.71 ccw(c2216.76,2348.55) 2221.6,2348.55 2221.6,2382.55 cw(c2239.04,2382.55) 2239.04,2399.99 2253.56,2399.99 cw(c2253.56,2382.55) 2271,2382.55 2271,2347.95 ccw(c2275.84,2347.95) 2275.84,2343.11 2290.36,2343.11 ccw(c2290.36,2347.95) 2295.2,2347.95 2295.2,2375.41 cw(c2312.64,2375.41) 2312.64,2392.85 2327.16,2392.85 cw(c2327.16,2375.41) 2344.6,2375.41 2344.6,2347.95 ccw(c2349.44,2347.95) 2349.44,2343.11 2363.96,2343.11 ccw(c2363.96,2347.95) 2368.8,2347.95 2368.8,2375.41 cw(c2386.24,2375.41) 2386.24,2392.85 2400.76,2392.85 cw(c2400.76,2375.41) 2418.2,2375.41 2418.2,2347.95 ccw(c2423.04,2347.95) 2423.04,2343.11 2437.56,2343.11 ccw(c2437.56,2347.95) 2442.4,2347.95 2442.4,2375.41 cw(c2459.84,2375.41) 2459.84,2392.85 2474.36,2392.85 cw(c2474.36,2375.41) 2491.8,2375.41 2491.8,2347.95 ccw(c2496.64,2347.95) 2496.64,2343.11 2511.16,2343.11 ccw(c2511.16,2347.95) 2516,2347.95 2516,2375.41 cw(c2533.44,2375.41) 2533.44,2392.85 2547.96,2392.85 cw(c2547.96,2375.41) 2565.4,2375.41 2565.4,2347.95 ccw(c2570.24,2347.95) 2570.24,2343.11 2584.76,2343.11 ccw(c2584.76,2347.95) 2589.6,2347.95 2589.6,2375.41 cw(c2607.04,2375.41) 2607.04,2392.85 2621.56,2392.85 cw(c2621.56,2375.41) 2639,2375.41 2639,2347.95 ccw(c2643.84,2347.95) 2643.84,2343.11 2658.36,2343.11 ccw(c2658.36,2347.95) 2663.2,2347.95 2663.2,2350.67 cw(c2680.64,2350.67) 2680.64,2368.11 2689.04,2368.11 2699.43,2368.11 2733.27,2334.27 2733.27,2098.11 3013.18,1818.2 3045.79,1818.2 3052.24,1811.74 3060.6,1803.39 ccw(c3064.02,1806.81) 3067.44,1803.39 3070.91,1806.86 cw(c3074.33,1803.44) 3077.76,1806.86 3088.02,1796.59 cw(c3084.6,1793.17) 3088.02,1789.75 3084.55,1786.28 ccw(c3087.98,1782.85) 3084.55,1779.43 3103.15,1760.83 3103.15,1728.23 3127.53,1703.85 3134.85,1703.85 3139.53,1708.53 3139.53,1715.53 v1(3142.17,1718.17)
PORTC_S13_D7P: J1.18 MC1.34 | length 2839.6
  L1-TOP w4.2: J1.18@1897.69,2643.11 1897.69,2606.36 1891.79,2600.46 1890.7,2600.46 1888.24,2598 1888.24,2552.17 1888.24,2389.41 2116.24,2161.42 2158.46,2161.42 2313.98,2161.42 2879.65,2161.42 2952.76,2161.42 2962.83,2171.49 2961.07,2173.25 v1(2961.07,2176.73) ; MC1.34@3257.89,1315.37 3261.43,1311.83 3261.43,1224.69 3304.31,1181.81 3302.55,1180.05 v1(3302.55,1176.57)
  L8-BOT w4.2: v1(2961.07,2176.73) 2958.43,2174.09 2958.43,2167.09 2948.28,2156.94 2948.28,2143.02 2948.47,2142.83 2948.47,2132.58 2967.66,2113.38 3049.9,2113.38 3173.23,1990.06 3173.23,1787.4 3255.91,1704.72 3255.91,1533.57 3203.94,1481.6 3203.94,1362.99 3272.37,1294.56 3272.37,1262.21 3272.37,1213.75 3299.91,1186.21 3299.91,1179.21 v1(3302.55,1176.57)
PORTC_S14_D6N: J1.19 MC1.31 | length 2793
  L1-TOP w4.2: v1(3158.08,1702.26) 3157.12,1701.31 3150.12,1701.31 3125.98,1677.17 3125.98,1661.42 3140.94,1646.46 3191.45,1646.46 3234.66,1603.25 3234.66,1562.22 MC1.31@3238.2,1558.68
  L8-BOT w4.2: v1(1870.36,2825.35) 1870.36,2821.61 1875.59,2816.38 1875.59,2796.51 1913.14,2758.96 1913.14,2741.42 2014.8,2639.77 2014.8,2492.4 2151.69,2355.51 2154.3,2355.51 2179.96,2355.51 cw(c2179.96,2350.67) 2184.8,2350.67 2184.8,2348.55 ccw(c2202.24,2348.55) 2202.24,2331.11 2216.76,2331.11 ccw(c2216.76,2348.55) 2234.2,2348.55 2234.2,2382.55 cw(c2239.04,2382.55) 2239.04,2387.39 2253.56,2387.39 cw(c2253.56,2382.55) 2258.4,2382.55 2258.4,2347.95 ccw(c2275.84,2347.95) 2275.84,2330.51 2290.36,2330.51 ccw(c2290.36,2347.95) 2307.8,2347.95 2307.8,2375.41 cw(c2312.64,2375.41) 2312.64,2380.25 2327.16,2380.25 cw(c2327.16,2375.41) 2332,2375.41 2332,2347.95 ccw(c2349.44,2347.95) 2349.44,2330.51 2363.96,2330.51 ccw(c2363.96,2347.95) 2381.4,2347.95 2381.4,2375.41 cw(c2386.24,2375.41) 2386.24,2380.25 2400.76,2380.25 cw(c2400.76,2375.41) 2405.6,2375.41 2405.6,2347.95 ccw(c2423.04,2347.95) 2423.04,2330.51 2437.56,2330.51 ccw(c2437.56,2347.95) 2455,2347.95 2455,2375.41 cw(c2459.84,2375.41) 2459.84,2380.25 2474.36,2380.25 cw(c2474.36,2375.41) 2479.2,2375.41 2479.2,2347.95 ccw(c2496.64,2347.95) 2496.64,2330.51 2511.16,2330.51 ccw(c2511.16,2347.95) 2528.6,2347.95 2528.6,2375.41 cw(c2533.44,2375.41) 2533.44,2380.25 2547.96,2380.25 cw(c2547.96,2375.41) 2552.8,2375.41 2552.8,2347.95 ccw(c2570.24,2347.95) 2570.24,2330.51 2584.76,2330.51 ccw(c2584.76,2347.95) 2602.2,2347.95 2602.2,2375.41 cw(c2607.04,2375.41) 2607.04,2380.25 2621.56,2380.25 cw(c2621.56,2375.41) 2626.4,2375.41 2626.4,2347.95 ccw(c2643.84,2347.95) 2643.84,2330.51 2658.36,2330.51 ccw(c2658.36,2347.95) 2675.8,2347.95 2675.8,2350.67 cw(c2680.64,2350.67) 2680.64,2355.51 2689.04,2355.51 2694.21,2355.51 2720.67,2329.05 2720.67,2092.89 3007.96,1805.6 3040.57,1805.6 3090.55,1755.61 3090.55,1723.01 3122.31,1691.25 3140.07,1691.25 3148.44,1699.62 3155.44,1699.62 v1(3158.08,1702.26)
PORTC_S15_D7N: J1.20 MC1.36 | length 2839.6
  L1-TOP w4.2: J1.20@1866.19,2643.11 1866.19,2606.36 1872.09,2600.46 1873.18,2600.46 1875.64,2598 1875.64,2552.17 1875.64,2384.2 2111.02,2148.82 2158.46,2148.82 2313.98,2148.82 2879.65,2148.82 2934.91,2148.82 2957.97,2148.82 2971.74,2162.58 2975.22,2162.58 v1(2976.98,2160.82) ; MC1.36@3277.57,1315.37 3274.03,1311.83 3274.03,1229.9 3313.22,1190.72 3316.7,1190.72 v1(3318.46,1192.48)
  L8-BOT w4.2: v1(2976.98,2160.82) 2974.34,2158.18 2967.34,2158.18 2960.88,2151.72 2960.88,2148.24 2961.07,2148.05 2961.07,2137.8 2972.88,2125.98 3055.12,2125.98 3185.83,1995.27 3185.83,1792.62 3268.51,1709.94 3268.51,1528.35 3216.54,1476.38 3216.54,1368.21 3284.97,1299.78 3284.97,1218.97 3308.82,1195.12 3315.82,1195.12 v1(3318.46,1192.48)
PORTC_S16: J1.21 MC1.27 | length 2789.9
  L1-TOP w4.5: v1(3198.83,1513.8) MC1.27@3198.83,1558.68
  L8-BOT w4.5: v1(1834.64,2912.06) 1834.64,2850.78 1832.05,2848.19 1832.05,2792.6 1947.83,2676.81 1947.83,2497.08 2131.92,2312.99 2676.18,2312.99 2691.93,2297.24 2691.93,2078.29 3000.4,1769.82 3032.25,1769.82 3070.87,1731.2 3070.87,1708.66 3128.33,1651.19 3189.99,1651.19 3218.28,1622.9 3218.28,1578.74 3196.63,1557.09 3149.61,1557.09 3082.68,1490.16 3082.68,1429.13 3092.24,1419.58 3136.37,1419.58 3143.69,1426.9 3143.69,1520.66 3155.51,1532.48 3180.15,1532.48 v1(3198.83,1513.8)
PORTC_S17: J1.22 MC1.32 | length 2790.2
  L1-TOP w4.5: v1(3238.17,1265.83) 3238.27,1265.93 MC1.32@3238.27,1315.44
  L8-BOT w4.5: v1(1834.64,2686.46) 1834.64,2667.18 ccw(c1839.54,2667.18) 1839.54,2662.28 1840.49,2662.28 cw(c1840.49,2657.38) 1845.39,2657.38 1845.39,2642.68 cw(c1840.49,2642.68) 1840.49,2637.78 1794.65,2637.78 ccw(c1794.65,2632.88) 1789.75,2632.88 1789.75,2618.18 ccw(c1794.65,2618.18) 1794.65,2613.28 1840.49,2613.28 cw(c1840.49,2608.38) 1845.39,2608.38 1845.39,2593.68 cw(c1840.49,2593.68) 1840.49,2588.78 1794.65,2588.78 ccw(c1794.65,2583.88) 1789.75,2583.88 1789.75,2569.18 ccw(c1794.65,2569.18) 1794.65,2564.28 1829.74,2564.28 cw(c1829.74,2559.38) 1834.64,2559.38 1834.64,2557.13 1834.64,2552.15 1834.64,2536.5 cw(c1829.74,2536.5) 1829.74,2531.6 1823.67,2531.6 ccw(c1823.67,2526.7) 1818.77,2526.7 1818.77,2512 ccw(c1823.67,2512) 1823.67,2507.1 1829.74,2507.1 cw(c1829.74,2502.2) 1834.64,2502.2 1834.64,2499.95 1834.64,2458.87 2186.24,2107.28 2214.83,2107.28 2256.11,2107.28 cw(c2256.11,2102.38) 2261.01,2102.38 2261.01,2097.9 ccw(c2265.91,2097.9) 2265.91,2093 2280.61,2093 ccw(c2280.61,2097.9) 2285.51,2097.9 2285.51,2102.38 cw(c2290.41,2102.38) 2290.41,2107.28 2305.11,2107.28 cw(c2305.11,2102.38) 2310.01,2102.38 2310.01,2087.18 ccw(c2314.91,2087.18) 2314.91,2082.28 2329.61,2082.28 ccw(c2329.61,2087.18) 2334.51,2087.18 2334.51,2102.38 cw(c2339.41,2102.38) 2339.41,2107.28 2354.11,2107.28 cw(c2354.11,2102.38) 2359.01,2102.38 2359.01,2087.18 ccw(c2363.91,2087.18) 2363.91,2082.28 2378.61,2082.28 ccw(c2378.61,2087.18) 2383.51,2087.18 2383.51,2102.38 cw(c2388.41,2102.38) 2388.41,2107.28 2403.11,2107.28 cw(c2403.11,2102.38) 2408.01,2102.38 2408.01,2087.18 ccw(c2412.91,2087.18) 2412.91,2082.28 2427.61,2082.28 ccw(c2427.61,2087.18) 2432.51,2087.18 2432.51,2102.38 cw(c2437.41,2102.38) 2437.41,2107.28 2452.11,2107.28 cw(c2452.11,2102.38) 2457.01,2102.38 2457.01,2087.18 ccw(c2461.91,2087.18) 2461.91,2082.28 2476.61,2082.28 ccw(c2476.61,2087.18) 2481.51,2087.18 2481.51,2102.38 cw(c2486.41,2102.38) 2486.41,2107.28 2501.11,2107.28 cw(c2501.11,2102.38) 2506.01,2102.38 2506.01,2087.18 ccw(c2510.91,2087.18) 2510.91,2082.28 2525.61,2082.28 ccw(c2525.61,2087.18) 2530.51,2087.18 2530.51,2102.38 cw(c2535.41,2102.38) 2535.41,2107.28 2537.66,2107.28 2557.09,2107.28 2584.88,2079.49 2584.88,2033.8 2876.94,1741.74 2876.94,1605.45 2995.05,1487.34 2995.05,1423.71 3040.39,1378.37 3157.07,1378.37 3238.17,1297.26 v1(3238.17,1265.83)
PORTC_S18: J1.23 MC1.25 | length 2790.1
  L1-TOP w4.5: v1(3165.37,1513.8) 3179.15,1527.57 MC1.25@3179.15,1558.68
  L8-BOT w4.5: v1(1803.14,2825.35) 1803.14,2805.39 1929.99,2678.54 1929.99,2489.68 2123.18,2296.49 2644.45,2296.49 2674.08,2266.86 2674.08,2070.89 2993,1751.97 3026.76,1751.97 3054.37,1724.36 3054.37,1701.83 3121.5,1634.69 3178.19,1634.69 3200.59,1612.3 3200.59,1589.37 3189.96,1578.74 3129.53,1578.74 3121.06,1578.74 3114.65,1572.33 ccw(c3118.12,1568.86) 3114.65,1565.4 cw(c3111.19,1561.93) 3114.65,1558.47 3104.26,1548.07 cw(c3100.79,1551.54) 3097.33,1548.07 3093.86,1551.54 ccw(c3090.4,1548.08) 3086.93,1551.54 3076.54,1541.15 ccw(c3080,1537.68) 3076.54,1534.22 3087.22,1523.53 cw(c3083.76,1520.07) 3087.22,1516.61 3076.83,1506.21 cw(c3073.36,1509.68) 3069.9,1506.21 3062.68,1513.43 ccw(c3059.21,1509.96) 3055.75,1513.43 3044.29,1501.97 3044.29,1490.52 3044.29,1423.23 3071.85,1395.67 3151.57,1395.67 3165.37,1409.46 v1(3165.37,1513.8)
PORTC_S19: J1.24 MC1.30 | length 2832.6
  L1-TOP w4.5: v1(1791.34,2493.11) 1763.78,2493.11 1748.03,2477.36 1748.03,2343.17 1765.41,2325.79 1824.11,2325.79 1839.57,2341.24 1839.57,2551.18 1803.19,2587.55 J1.24@1803.19,2643.11 ; v1(3218.36,1225.72) 3218.52,1225.88 MC1.30@3218.52,1315.37
  L8-BOT w4.5: v1(1791.34,2493.11) 1810.01,2493.11 1818.14,2484.98 1818.14,2451.76 2204.82,2065.08 2548.57,2065.08 2568.38,2045.28 2568.38,2026.83 2860.34,1734.86 2860.34,1598.58 2978.45,1480.47 2978.45,1416.83 3033.07,1362.2 3145.67,1362.2 3218.36,1289.52 v1(3218.36,1225.72)
PORTC_S20: J1.25 MC1.23 | length 2790.1
  L1-TOP w4.5: MC1.23@3159.46,1558.68 v1(3159.46,1606.3)
  L8-BOT w4.5: v1(1771.64,2912.06) 1771.64,2909.42 1771.64,2897.59 ccw(c1776.54,2897.59) 1776.54,2892.69 1813.94,2892.69 cw(c1813.94,2887.79) 1818.84,2887.79 1818.84,2873.09 cw(c1813.94,2873.09) 1813.94,2868.19 1725.55,2868.19 ccw(c1725.55,2863.29) 1720.65,2863.29 1720.65,2848.59 ccw(c1725.55,2848.59) 1725.55,2843.69 1766.74,2843.69 cw(c1766.74,2838.79) 1771.64,2838.79 1771.64,2836.54 1771.64,2832.67 1757.71,2818.73 1757.71,2798.39 1776.57,2779.53 1812.94,2779.53 1913.39,2679.08 1913.39,2482.81 2103.61,2292.59 2103.75,2292.59 2116.34,2279.99 2303.83,2279.99 2311.09,2272.73 2311.09,2255.02 2315.92,2250.19 2317.09,2249.02 2330.9,2249.02 ccw(c2330.9,2253.92) 2335.8,2253.92 cw(c2340.7,2253.92) 2340.7,2258.82 2355.4,2258.82 cw(c2355.4,2253.92) 2360.3,2253.92 ccw(c2365.2,2253.92) 2365.2,2249.02 2379.9,2249.02 ccw(c2379.9,2253.92) 2384.8,2253.92 2384.8,2271.86 cw(c2389.7,2271.86) 2389.7,2276.76 2404.4,2276.76 cw(c2404.4,2271.86) 2409.3,2271.86 2409.3,2253.92 ccw(c2414.2,2253.92) 2414.2,2249.02 2428.9,2249.02 ccw(c2428.9,2253.92) 2433.8,2253.92 2433.8,2275.09 cw(c2438.7,2275.09) 2438.7,2279.99 2453.4,2279.99 cw(c2453.4,2275.09) 2458.3,2275.09 2458.3,2253.92 ccw(c2463.2,2253.92) 2463.2,2249.02 2477.9,2249.02 ccw(c2477.9,2253.92) 2482.8,2253.92 2482.8,2275.09 cw(c2487.7,2275.09) 2487.7,2279.99 2502.4,2279.99 cw(c2502.4,2275.09) 2507.3,2275.09 2507.3,2253.92 ccw(c2512.2,2253.92) 2512.2,2249.02 2526.9,2249.02 ccw(c2526.9,2253.92) 2531.8,2253.92 2531.8,2275.09 cw(c2536.7,2275.09) 2536.7,2279.99 2551.4,2279.99 cw(c2551.4,2275.09) 2556.3,2275.09 2556.3,2253.92 ccw(c2561.2,2253.92) 2561.2,2249.02 2575.9,2249.02 ccw(c2575.9,2253.92) 2580.8,2253.92 2580.8,2275.09 cw(c2585.7,2275.09) 2585.7,2279.99 2600.4,2279.99 cw(c2600.4,2275.09) 2605.3,2275.09 2605.3,2234.98 ccw(c2610.2,2234.98) 2610.2,2230.08 2624.9,2230.08 ccw(c2624.9,2234.98) 2629.8,2234.98 2629.8,2244.12 cw(c2634.7,2244.12) 2634.7,2249.02 2636.95,2249.02 2645.18,2249.02 2657.48,2236.72 2657.48,2064.02 2988.17,1733.32 3018.59,1733.32 3035.57,1716.34 3035.57,1697.29 3126.56,1606.3 v1(3159.46,1606.3)
PORTC_S21: J1.26 MC1.28 | length 2790.2
  L1-TOP w4.5: v1(3198.8,1265.83) 3198.9,1265.93 MC1.28@3198.9,1315.44
  L8-BOT w4.5: v1(1771.64,2686.46) 1773.13,2687.95 1773.13,2697.71 1778.31,2702.9 1787.11,2702.9 1805.91,2684.09 1805.91,2670.89 1800.91,2665.89 1727.69,2665.89 1712.44,2650.64 1688.48,2650.64 1680.37,2642.53 1680.37,2634.85 1684.31,2630.91 1704.72,2630.91 1714.73,2620.9 1757.05,2620.9 1765.3,2612.65 1765.3,2479.69 2218.41,2026.57 2228.22,2026.57 2380.02,2026.57 ccw(c2380.02,2031.47) 2384.92,2031.47 2384.92,2040.07 cw(c2389.82,2040.07) 2389.82,2044.97 2404.52,2044.97 cw(c2404.52,2040.07) 2409.42,2040.07 2409.42,2007.62 ccw(c2414.32,2007.62) 2414.32,2002.72 2429.02,2002.72 ccw(c2429.02,2007.62) 2433.92,2007.62 2433.92,2043.68 cw(c2438.82,2043.68) 2438.82,2048.58 2453.52,2048.58 cw(c2453.52,2043.68) 2458.42,2043.68 2458.42,2007.62 ccw(c2463.32,2007.62) 2463.32,2002.72 2478.02,2002.72 ccw(c2478.02,2007.62) 2482.92,2007.62 2482.92,2043.68 cw(c2487.82,2043.68) 2487.82,2048.58 2502.52,2048.58 cw(c2502.52,2043.68) 2507.42,2043.68 2507.42,2007.62 ccw(c2512.32,2007.62) 2512.32,2002.72 2527.02,2002.72 ccw(c2527.02,2007.62) 2531.92,2007.62 2531.92,2021.67 cw(c2536.82,2021.67) 2536.82,2026.57 2539.07,2026.57 2543.43,2026.57 2842.52,1727.48 2842.52,1591.2 2960.63,1473.09 2960.63,1409.45 3023.62,1346.46 3133.17,1346.46 3198.8,1280.82 v1(3198.8,1265.83)
PORTC_S22: J1.27 MC1.21 | length 2790.1
  L1-TOP w4.5: v1(2988.19,1704.72) 3007.87,1685.04 3057.04,1685.04 3139.78,1602.3 MC1.21@3139.78,1558.68
  L8-BOT w4.5: v1(1740.14,2825.35) 1740.14,2804.37 1729.45,2793.68 1729.45,2779.46 1736.18,2772.73 1766.7,2772.73 1780.02,2759.41 1780.02,2746.35 1786.77,2739.6 1837.82,2739.6 1895.67,2681.75 1895.67,2475.47 2157.56,2213.58 2161.19,2213.58 2194.01,2213.58 ccw(c2194.01,2218.48) 2198.91,2218.48 2198.91,2232.11 cw(c2203.81,2232.11) 2203.81,2237.01 2218.51,2237.01 cw(c2218.51,2232.11) 2223.41,2232.11 2223.41,2199.55 ccw(c2228.31,2199.55) 2228.31,2194.65 2243.01,2194.65 ccw(c2243.01,2199.55) 2247.91,2199.55 2247.91,2253.34 cw(c2252.81,2253.34) 2252.81,2258.24 2267.51,2258.24 cw(c2267.51,2253.34) 2272.41,2253.34 2272.41,2199.55 ccw(c2277.31,2199.55) 2277.31,2194.65 2292.01,2194.65 ccw(c2292.01,2199.55) 2296.91,2199.55 2296.91,2227.62 cw(c2301.81,2227.62) 2301.81,2232.52 2316.51,2232.52 cw(c2316.51,2227.62) 2321.41,2227.62 2321.41,2199.55 ccw(c2326.31,2199.55) 2326.31,2194.65 2341.01,2194.65 ccw(c2341.01,2199.55) 2345.91,2199.55 2345.91,2227.62 cw(c2350.81,2227.62) 2350.81,2232.52 2365.51,2232.52 cw(c2365.51,2227.62) 2370.41,2227.62 2370.41,2199.55 ccw(c2375.31,2199.55) 2375.31,2194.65 2390.01,2194.65 ccw(c2390.01,2199.55) 2394.91,2199.55 2394.91,2227.62 cw(c2399.81,2227.62) 2399.81,2232.52 2414.51,2232.52 cw(c2414.51,2227.62) 2419.41,2227.62 2419.41,2199.55 ccw(c2424.31,2199.55) 2424.31,2194.65 2439.01,2194.65 ccw(c2439.01,2199.55) 2443.91,2199.55 2443.91,2227.62 cw(c2448.81,2227.62) 2448.81,2232.52 2463.51,2232.52 cw(c2463.51,2227.62) 2468.41,2227.62 2468.41,2199.55 ccw(c2473.31,2199.55) 2473.31,2194.65 2488.01,2194.65 ccw(c2488.01,2199.55) 2492.91,2199.55 2492.91,2227.62 cw(c2497.81,2227.62) 2497.81,2232.52 2512.51,2232.52 cw(c2512.51,2227.62) 2517.41,2227.62 2517.41,2199.55 ccw(c2522.31,2199.55) 2522.31,2194.65 2537.01,2194.65 ccw(c2537.01,2199.55) 2541.91,2199.55 2541.91,2227.62 cw(c2546.81,2227.62) 2546.81,2232.52 2561.51,2232.52 cw(c2561.51,2227.62) 2566.41,2227.62 2566.41,2199.55 ccw(c2571.31,2199.55) 2571.31,2194.65 2586.01,2194.65 ccw(c2586.01,2199.55) 2590.91,2199.55 2590.91,2208.68 cw(c2595.81,2208.68) 2595.81,2213.58 2598.06,2213.58 2607.33,2213.58 2639.76,2181.15 2639.76,2056.68 2988.19,1708.25 v1(2988.19,1704.72)
PORTC_S23: J1.28 MC1.26 | length 2790.1
  L1-TOP w4.5: v1(3178.98,1225.72) 3179.15,1225.88 MC1.26@3179.15,1315.37
  L8-BOT w4.5: v1(1740.14,2599.75) 1740.14,2551.91 1740.14,2539.27 cw(c1735.24,2539.27) 1735.24,2534.37 1719.15,2534.37 ccw(c1719.15,2529.47) 1714.25,2529.47 1714.25,2514.77 ccw(c1719.15,2514.77) 1719.15,2509.87 1735.24,2509.87 cw(c1735.24,2504.97) 1740.14,2504.97 1740.14,2502.72 1740.14,2481.36 2220.98,2000.53 2235.29,1986.22 2321.54,1986.22 cw(c2321.54,1981.32) 2326.44,1981.32 2326.44,1940.55 ccw(c2331.34,1940.55) 2331.34,1935.65 2346.04,1935.65 ccw(c2346.04,1940.55) 2350.94,1940.55 2350.94,1995.35 cw(c2355.84,1995.35) 2355.84,2000.25 2370.54,2000.25 cw(c2370.54,1995.35) 2375.44,1995.35 2375.44,1922.97 ccw(c2380.34,1922.97) 2380.34,1918.07 2395.04,1918.07 ccw(c2395.04,1922.97) 2399.94,1922.97 2399.94,1981.32 cw(c2404.84,1981.32) 2404.84,1986.22 2419.54,1986.22 cw(c2419.54,1981.32) 2424.44,1981.32 2424.44,1957.75 ccw(c2429.34,1957.75) 2429.34,1952.85 2444.04,1952.85 ccw(c2444.04,1957.75) 2448.94,1957.75 2448.94,1981.32 cw(c2453.84,1981.32) 2453.84,1986.22 2468.54,1986.22 cw(c2468.54,1981.32) 2473.44,1981.32 2473.44,1958.42 ccw(c2478.34,1958.42) 2478.34,1953.52 2493.04,1953.52 ccw(c2493.04,1958.42) 2497.94,1958.42 2497.94,1981.32 cw(c2502.84,1981.32) 2502.84,1986.22 2517.54,1986.22 cw(c2517.54,1981.32) 2522.44,1981.32 2522.44,1959.32 ccw(c2527.34,1959.32) 2527.34,1954.42 2542.04,1954.42 ccw(c2542.04,1959.32) 2546.94,1959.32 2546.94,1981.32 cw(c2551.84,1981.32) 2551.84,1986.22 2554.09,1986.22 2560.45,1986.22 2824.34,1722.33 2824.34,1498.5 2843.63,1479.2 2866.68,1479.2 3019.11,1326.77 3128.12,1326.77 3178.98,1275.91 v1(3178.98,1225.72)
PORTC_S24: J1.29 MC1.19 | length 2790.1
  L1-TOP w4.5: v1(3018.7,1651.57) 3018.7,1648.95 3033.79,1633.86 3079.31,1633.86 3120.09,1593.08 MC1.19@3120.09,1558.68
  L8-BOT w4.5: v1(1708.64,2912.06) 1708.64,2909.02 1702.3,2902.68 1702.3,2784.95 1757.97,2729.28 1832.48,2729.28 1875,2686.76 1875,2466.91 2163.76,2178.15 2604.33,2178.15 2619.09,2163.39 2619.09,2048.12 2950.79,1716.42 2950.79,1644.69 2922.36,1616.26 2922.36,1603.23 2923.95,1601.64 2930.95,1594.64 ccw(c2934.42,1598.1) 2937.88,1594.64 2959.43,1616.19 cw(c2962.9,1612.73) 2966.36,1616.19 2976.76,1605.8 cw(c2973.29,1602.33) 2976.76,1598.87 2948.25,1570.36 ccw(c2951.71,1566.89) 2948.25,1563.43 2958.64,1553.03 ccw(c2962.11,1556.5) 2965.57,1553.03 2995.92,1583.38 cw(c2999.38,1579.91) 3002.85,1583.38 3013.24,1572.98 cw(c3009.78,1569.52) 3013.24,1566.06 2982.9,1535.71 ccw(c2986.36,1532.24) 2982.9,1528.78 2993.29,1518.39 ccw(c2996.76,1521.85) 3000.22,1518.39 ; 3000.25,1518.41 cw(c3003.71,1514.95) 3007.18,1518.41 3008.77,1516.82 3012.35,1513.24 3023.67,1513.24 3050.25,1539.81 3050.25,1563.99 3017.72,1596.52 3017.72,1633.86 3017.72,1650.59 v1(3018.7,1651.57)
PORTC_S25: J1.30 MC1.24 | length 2790.3
  L1-TOP w4.5: v1(3159.43,1265.83) 3159.53,1265.93 3159.53,1315.44 MC1.24@3159.63,1315.53
  L8-BOT w4.5: v1(1708.64,2686.46) 1707.7,2685.52 1691.79,2685.52 1684.06,2677.78 1684.06,2668.83 1672.79,2657.56 1588.46,2657.56 1581.69,2650.8 1581.69,2580.71 1611.22,2551.18 1625,2551.18 1635.83,2562.01 1635.83,2593.44 1660.5,2618.11 1694.42,2618.11 1702.3,2610.24 1702.3,2495.74 2296.46,1901.57 2437.73,1901.57 2446.96,1910.81 2446.96,1930.39 2453.59,1937.02 2463.32,1937.02 2474.49,1937.02 cw(c2474.49,1932.12) 2479.39,1932.12 2479.39,1919.94 ccw(c2484.29,1919.94) 2484.29,1915.04 2498.99,1915.04 ccw(c2498.99,1919.94) 2503.89,1919.94 2503.89,1933.02 cw(c2508.79,1933.02) 2508.79,1937.92 2523.49,1937.92 cw(c2523.49,1933.02) 2528.39,1933.02 2528.39,1912.28 ccw(c2533.29,1912.28) 2533.29,1907.38 2547.99,1907.38 ccw(c2547.99,1912.28) 2552.89,1912.28 2552.89,1932.12 cw(c2557.79,1932.12) 2557.79,1937.02 2560.04,1937.02 2586.31,1937.02 2807.84,1715.5 2807.84,1491.66 2830.85,1468.65 2836.8,1462.7 2859.93,1462.7 3011.61,1311.02 3114.24,1311.02 v1(3159.43,1265.83)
